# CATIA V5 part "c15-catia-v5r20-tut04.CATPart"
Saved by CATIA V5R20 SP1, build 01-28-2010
Part number: Part1
Bounding box of the stored display mesh (mm): x -3 to 154, y -3 to 154, z -47 to 3.015
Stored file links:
  D:\v5_r20\psrt_files_downloaded\c15-catia-v5r20-prt\c15-catia-v5r20-tut04.CATPart
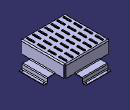
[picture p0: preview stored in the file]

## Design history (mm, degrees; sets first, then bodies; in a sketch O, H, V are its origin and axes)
SheetMetalParameters1: Thickness 1, BendRadius 2, KFactor 0.400515 {= log(min(100,max(20*SheetMetalParameters1.BendRadius,SheetMetalParameters1.Thickness)/SheetMetalParameters1.Thickness))/log(100)/2}, ReliefRadialLength 1, ReliefAxialLength 2, MinimumBendRadius 0
Body1 (main body)
  Sketch1 on xy-plane, origin (0, 0, 0), H (1, 0, 0), V (0, 1, 0)
    line L1 (0, 0) -> (120, 0)
    line L2 (120, 0) -> (120, 120)
    line L3 (120, 120) -> (0, 120)
    line L4 (0, 120) -> (0, 0)
    length L3 = 120
    length L2 = 120
    horizontal: L1 H, L3 H
    vertical: L2 V, L4 V
  Wall1: Thickness 1, Profile Sketch1
  Flange1: Angle 90, Length 34, Radius 2, KFacteur 0.400515 {= log(min(100,max(20*Flange1.Radius,SheetMetalParameters1.Thickness)/SheetMetalParameters1.Thickness))/log(100)/2}, Guide edge [face of Wall1 | face of Wall1]
  Flange2: Angle 90, Length 34, Radius 2, KFacteur 0.400515 {= log(min(100,max(20*Flange2.Radius,SheetMetalParameters1.Thickness)/SheetMetalParameters1.Thickness))/log(100)/2}, Guide edge [face of Wall1 | face of Wall1]
  Flange3: Angle 90, Length 34, Radius 2, KFacteur 0.400515 {= log(min(100,max(20*Flange3.Radius,SheetMetalParameters1.Thickness)/SheetMetalParameters1.Thickness))/log(100)/2}, Guide edge [face of Wall1 | face of Wall1]
  Flange4: Angle 90, Length 34, Radius 2, KFacteur 0.400515 {= log(min(100,max(20*Flange4.Radius,SheetMetalParameters1.Thickness)/SheetMetalParameters1.Thickness))/log(100)/2}, Guide edge [face of Wall1 | face of Wall1]
  d_NewWallOnEdge1: NewWallOnEdge_Edge edge [face of Flange3 | face of Flange3], NewWallOnEdge_Length 21, NewWallOnEdge_HeightLimitOffset 0, NewWallOnEdge_WidthOffset1 -25, NewWallOnEdge_WidthOffset2 -25, NewWallOnEdge_Angle 90, NewWallOnEdge_BendRadiusValue 2 {= SheetMetalParameters1.BendRadius}, NewWallOnEdge_BendTable SheetMetalParameters1, KFacteur 0.400515 {= log(min(100,max(20*d_NewWallOnEdge1.Radius,SheetMetalParameters1.Thickness)/SheetMetalParameters1.Thickness))/log(100)/2}
  Flange5: Angle 90, Length 13, Radius 1, KFacteur 0.325257 {= log(min(100,max(20*Flange5.Radius,SheetMetalParameters1.Thickness)/SheetMetalParameters1.Thickness))/log(100)/2}, Guide edge [face of d_NewWallOnEdge1 | face of d_NewWallOnEdge1]
  d_NewWallOnEdge2: NewWallOnEdge_Edge edge [face of Flange5 | face of Flange5], NewWallOnEdge_Length 10, NewWallOnEdge_HeightLimitOffset 0, NewWallOnEdge_WidthOffset1 0, NewWallOnEdge_WidthOffset2 0, NewWallOnEdge_Angle 90, NewWallOnEdge_BendRadiusValue 2 {= SheetMetalParameters1.BendRadius}, NewWallOnEdge_BendTable SheetMetalParameters1, KFacteur 0.400515 {= log(min(100,max(20*d_NewWallOnEdge2.Radius,SheetMetalParameters1.Thickness)/SheetMetalParameters1.Thickness))/log(100)/2}
  d_NewWallOnEdge3: NewWallOnEdge_Edge edge [face of Flange2 | face of Flange2], NewWallOnEdge_Length 21, NewWallOnEdge_HeightLimitOffset 0, NewWallOnEdge_WidthOffset1 -25, NewWallOnEdge_WidthOffset2 -25, NewWallOnEdge_Angle 90, NewWallOnEdge_BendRadiusValue 2 {= SheetMetalParameters1.BendRadius}, NewWallOnEdge_BendTable SheetMetalParameters1, KFacteur 0.400515 {= log(min(100,max(20*d_NewWallOnEdge3.Radius,SheetMetalParameters1.Thickness)/SheetMetalParameters1.Thickness))/log(100)/2}
  Flange6: Angle 90, Length 13, Radius 1, KFacteur 0.325257 {= log(min(100,max(20*Flange6.Radius,SheetMetalParameters1.Thickness)/SheetMetalParameters1.Thickness))/log(100)/2}, Guide edge [face of d_NewWallOnEdge3 | face of d_NewWallOnEdge3]
  d_NewWallOnEdge4: NewWallOnEdge_Edge edge [face of Flange6 | face of Flange6], NewWallOnEdge_Length 10, NewWallOnEdge_HeightLimitOffset 0, NewWallOnEdge_WidthOffset1 0, NewWallOnEdge_WidthOffset2 0, NewWallOnEdge_Angle 90, NewWallOnEdge_BendRadiusValue 2 {= SheetMetalParameters1.BendRadius}, NewWallOnEdge_BendTable SheetMetalParameters1, KFacteur 0.400515 {= log(min(100,max(20*d_NewWallOnEdge4.Radius,SheetMetalParameters1.Thickness)/SheetMetalParameters1.Thickness))/log(100)/2}
  Sketch2 on face of d_NewWallOnEdge2, origin (31.3691, 147.6369, -46), H (1, 0, 0), V (0, 1, 0)
    point P1 (-1.3691, 2.3631)
    reference projected line E1 (-6.3691, 6.3631) -> (63.6309, 6.3631) from edge [face of d_NewWallOnEdge2 | face of d_NewWallOnEdge2]
    reference projected line E2 (-6.3691, -0.6369) -> (-6.3691, 6.3631) from edge [face of d_NewWallOnEdge2 | face of d_NewWallOnEdge2]
    distance P1 E1 = 4
    distance P1 E2 = 5
  Hole1: placed by Sketch2, at (30, 150, -46) direction (0, 0, -1), diameter 3, through (limit type 6)
  Sketch3 on face of d_NewWallOnEdge2, origin (79.2942, 150.7856, -46), H (1, 0, 0), V (0, 1, 0)
    point P1 (10.7058, -0.7856)
    reference projected line E1 (-54.2942, 3.2144) -> (15.7058, 3.2144) from edge [face of d_NewWallOnEdge2 | face of d_NewWallOnEdge2]
    reference projected line E2 (15.7058, 3.2144) -> (15.7058, -3.7856) from edge [face of d_NewWallOnEdge2 | face of d_NewWallOnEdge2]
    distance P1 E1 = 4
    distance P1 E2 = 5
  Hole2: placed by Sketch3, at (90, 150, -46) direction (0, 0, -1), diameter 3, through (limit type 6)
  Sketch4 on face of d_NewWallOnEdge4, origin (148.0642, 84.3582, -46), H (1, 0, 0), V (0, 1, 0)
    point P1 (1.9358, 5.6418)
    reference projected line E1 (5.9358, 10.6418) -> (5.9358, -59.3582) from edge [face of d_NewWallOnEdge4 | face of d_NewWallOnEdge4]
    reference projected line E2 (-1.0642, 10.6418) -> (5.9358, 10.6418) from edge [face of d_NewWallOnEdge4 | face of d_NewWallOnEdge4]
    distance P1 E1 = 4
    distance P1 E2 = 5
  Hole3: placed by Sketch4, at (150, 90, -46) direction (0, 0, -1), diameter 3, through (limit type 6)
  Sketch5 on face of d_NewWallOnEdge4, origin (149.1042, 61.7681, -46), H (1, 0, 0), V (0, 1, 0)
    point P1 (0.8958, -31.7681)
    reference projected line E1 (4.8958, -36.7681) -> (-2.1042, -36.7681) from edge [face of d_NewWallOnEdge4 | face of d_NewWallOnEdge4]
    reference projected line E2 (4.8958, 33.2319) -> (4.8958, -36.7681) from edge [face of d_NewWallOnEdge4 | face of d_NewWallOnEdge4]
    distance E1 P1 = 5
    distance P1 E2 = 4
  Hole4: placed by Sketch5, at (150, 30, -46) direction (0, 0, -1), diameter 3, through (limit type 6)
  Sketch6 on face of Wall1, origin (0, 0, 0), H (1, 0, 0), V (0, -1, 0)
    line L1 (112, -115) -> (109.5, -115)
    line L2 (109.5, -115) -> (109.5, -95)
    line L3 (109.5, -95) -> (112, -95)
    line L4 (112, -95) -> (112, -115)
    reference projected line E1 (0, -123) -> (120, -123) from edge [face of Flange3 | face of Flange3]
    reference projected line E2 (123, -120) -> (123, 0) from edge [face of Flange2 | face of Flange2]
    distance L2 L4 = 2.5
    length L2 = 20
    distance L1 E1 = 8
    distance L4 E2 = 11
    horizontal: L1 H, L3 H
    vertical: L2 V, L4 V
  d_Stamp1: NewRoot_AttribNormalisation "No Standard", Stamp_FilletRadius 0.25
  RectPattern1: of d_Stamp1, direction 1 instances 7, spacing 17, along edge [face of Flange3 | face of Flange3] reversed, direction 2 instances 4, spacing 30, along edge [face of Flange2 | face of Flange2]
